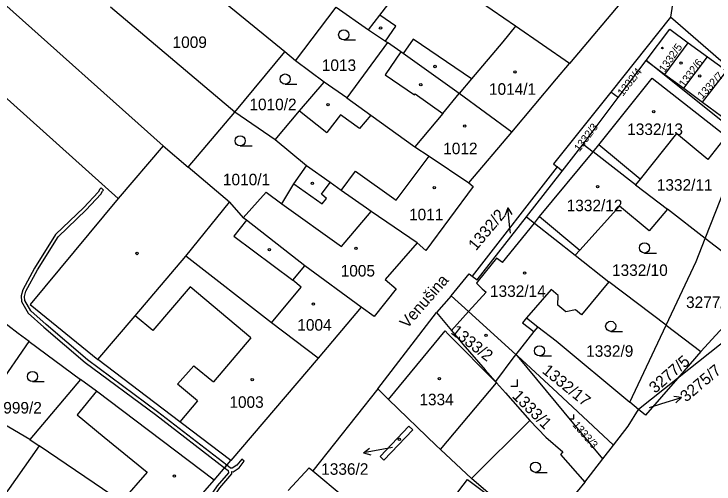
# Model space of a CAD drawing. Extents: x -600849 to -599899, y -1204328 to -1203436.
# Drawn here: x -600187.5 to -600084.4, y -1203603.2 to -1203534 of the extents above; entities that cross this region are included whole.
import ezdxf

# ---------------------------------------------------------------- set-up
doc = ezdxf.new("R2010")
doc.units = 0
for name, color, linetype in [('Vrstva 1', 7, 'Continuous'), ('Vrstva 13', 7, 'Continuous'), ('Vrstva 2', 7, 'Continuous'), ('Vrstva 3', 7, 'Continuous'), ('Vrstva 4', 7, 'Continuous'), ('Vrstva 5', 7, 'Continuous'), ('Vrstva 7', 7, 'Continuous')]:
    doc.layers.add(name, color=color, linetype=linetype)

msp = doc.modelspace()

# ---------------------------------------------------------------- linework, layer by layer
at = {"layer": 'Vrstva 1'}
for p, q in [((-600088.22, -1203518.34), (-600090.77, -1203534.42)), ((-600147.59, -1203539.56), (-600166.14, -1203524.37)), ((-600096.63, -1203530.54), (-600105.64, -1203541.26)), ((-600154.95, -1203548.45), (-600173.29, -1203532.96)), ((-600146.02, -1203540.85), (-600140.01, -1203532.98)), ((-600140.01, -1203532.98), (-600135.28, -1203536.29)), ((-600090.77, -1203534.42), (-600099.57, -1203545.46)), ((-600077.65, -1203545.83), (-600090.77, -1203534.42)), ((-600132.47, -1203538.17), (-600138.44, -1203546.32)), ((-600130.49, -1203539.53), (-600132.47, -1203538.17)), ((-600091.58, -1203542.86), (-600088.16, -1203538.23)), ((-600088.16, -1203538.23), (-600085.32, -1203540.29)), ((-600154.95, -1203548.45), (-600147.59, -1203539.56)), ((-600146.02, -1203540.85), (-600147.59, -1203539.56)), ((-600141.8, -1203544), (-600146.02, -1203540.85)), ((-600098.47, -1203546.28), (-600094.36, -1203540.81)), ((-600094.36, -1203540.81), (-600091.58, -1203542.86)), ((-600080.84, -1203551.64), (-600094.36, -1203540.81)), ((-600088.8, -1203544.91), (-600085.32, -1203540.29)), ((-600085.32, -1203540.29), (-600082.46, -1203542.35)), ((-600107.54, -1203543.52), (-600105.64, -1203541.26)), ((-600091.58, -1203542.86), (-600088.8, -1203544.91)), ((-600086.05, -1203546.94), (-600082.46, -1203542.35)), ((-600138.44, -1203546.32), (-600141.8, -1203544)), ((-600114.12, -1203551.39), (-600107.54, -1203543.52)), ((-600088.8, -1203544.91), (-600086.05, -1203546.94)), ((-600098.47, -1203546.28), (-600099.57, -1203545.46)), ((-600103.65, -1203553.16), (-600098.47, -1203546.28)), ((-600086.05, -1203546.94), (-600083.23, -1203549.02)), ((-600149.03, -1203552.52), (-600154.95, -1203548.45)), ((-600120.49, -1203558.87), (-600114.12, -1203551.39)), ((-600144.41, -1203556.36), (-600149.03, -1203552.52)), ((-600106.74, -1203557.12), (-600103.65, -1203553.16)), ((-600103.65, -1203553.16), (-600102.18, -1203554.3)), ((-600095.91, -1203559.13), (-600102.18, -1203554.3)), ((-600085.66, -1203567.04), (-600080.38, -1203553.65)), ((-600107.48, -1203556.49), (-600119.97, -1203572.62)), ((-600111.99, -1203563.84), (-600106.74, -1203557.12)), ((-600106.74, -1203557.12), (-600107.48, -1203556.49)), ((-600095.91, -1203559.13), (-600091.22, -1203562.75)), ((-600162.19, -1203569.64), (-600155.76, -1203561.69)), ((-600155.76, -1203561.69), (-600153.74, -1203564)), ((-600085.66, -1203567.04), (-600091.22, -1203562.75)), ((-600186.88, -1203581.05), (-600208.82, -1203564.15)), ((-600077.11, -1203573.64), (-600085.66, -1203567.04)), ((-600104.82, -1203569.52), (-600099.85, -1203573.46)), ((-600136.36, -1203577.15), (-600144.64, -1203571.07)), ((-600091.41, -1203579.85), (-600099.85, -1203573.46)), ((-600077.11, -1203573.64), (-600086.3, -1203583.72)), ((-600072.84, -1203574.2), (-600089.73, -1203587.68)), ((-600123.08, -1203575.5), (-600125.26, -1203577.97)), ((-600136.36, -1203577.15), (-600142.67, -1203584.7)), ((-600133.89, -1203589.22), (-600125.26, -1203577.97)), ((-600096.73, -1203591.19), (-600091.41, -1203579.85)), ((-600091.41, -1203579.85), (-600086.3, -1203583.72)), ((-600185.28, -1203582.21), (-600186.88, -1203581.05)), ((-600192.36, -1203592.5), (-600185.28, -1203582.21)), ((-600185.28, -1203582.21), (-600177.68, -1203587.81)), ((-600121.34, -1203582.61), (-600118.07, -1203586.41)), ((-600113.54, -1203584.13), (-600113.3, -1203584.33)), ((-600086.3, -1203583.72), (-600089.73, -1203587.68)), ((-600142.67, -1203584.7), (-600155.53, -1203599.75)), ((-600100.72, -1203599.54), (-600113.3, -1203584.33)), ((-600118.07, -1203586.41), (-600116.55, -1203588.13)), ((-600177.68, -1203587.81), (-600185.17, -1203596.68)), ((-600116.55, -1203588.13), (-600116.38, -1203588.32)), ((-600089.73, -1203587.68), (-600095.46, -1203592.25)), ((-600133.89, -1203589.22), (-600143.47, -1203601.31)), ((-600095.46, -1203592.25), (-600096.73, -1203591.19)), ((-600185.17, -1203596.68), (-600192.36, -1203592.5)), ((-600097, -1203594.73), (-600095.46, -1203592.25)), ((-600155.53, -1203599.75), (-600162.86, -1203594.2)), ((-600120.07, -1203602.44), (-600111.47, -1203593.9)), ((-600099.16, -1203597.53), (-600097, -1203594.73)), ((-600183.79, -1203597.62), (-600190.77, -1203607.52)), ((-600185.17, -1203596.68), (-600183.79, -1203597.62)), ((-600100.72, -1203599.54), (-600099.16, -1203597.53)), ((-600158.02, -1203602.67), (-600155.53, -1203599.75)), ((-600103.38, -1203602.99), (-600100.72, -1203599.54)), ((-600143.47, -1203601.31), (-600139.01, -1203605.01)), ((-600165.19, -1203610.87), (-600158.02, -1203602.67)), ((-600114.6, -1203607.12), (-600120.07, -1203602.44)), ((-600103.38, -1203602.99), (-600110.42, -1203611.48))]:
    msp.add_line(p, q, dxfattribs=at)
for points in [[(-600105.64, -1203541.26), (-600113.61, -1203535.76), (-600122.21, -1203529.82)], [(-600135.28, -1203536.29), (-600132.77, -1203537.97), (-600132.47, -1203538.17)], [(-600094.36, -1203540.81), (-600090.84, -1203536.22), (-600088.16, -1203538.23)], [(-600114.12, -1203551.39), (-600121.92, -1203545.7), (-600130.13, -1203539.79), (-600130.49, -1203539.53)], [(-600149.03, -1203552.52), (-600145.42, -1203548.24), (-600141.8, -1203544)], [(-600102.18, -1203554.3), (-600101.32, -1203553.26), (-600093.47, -1203543.4), (-600082.56, -1203551.95), (-600085.25, -1203555.41), (-600089.86, -1203551.56), (-600095.24, -1203558.29), (-600095.91, -1203559.13)], [(-600099.57, -1203545.46), (-600108, -1203556.04), (-600107.48, -1203556.49)], [(-600138.44, -1203546.32), (-600134.94, -1203548.85), (-600128.45, -1203553.54), (-600126.33, -1203554.94), (-600120.49, -1203558.87)], [(-600155.76, -1203561.69), (-600161.82, -1203556.56), (-600154.95, -1203548.45)], [(-600153.74, -1203564), (-600150.35, -1203560.2), (-600148.03, -1203561.92), (-600146.27, -1203559), (-600144.41, -1203556.36)], [(-600135.54, -1203562.6), (-600139.28, -1203559.96), (-600140.91, -1203558.81), (-600144.41, -1203556.36)], [(-600120.49, -1203558.87), (-600119.84, -1203559.41), (-600126.79, -1203568.8), (-600128.11, -1203567.7)], [(-600128.11, -1203567.7), (-600134.85, -1203563.07), (-600135.54, -1203562.6)], [(-600091.22, -1203562.75), (-600093.9, -1203565.92), (-600098.3, -1203562.3), (-600104.13, -1203568.75), (-600104.82, -1203569.52)], [(-600144.64, -1203571.07), (-600153.26, -1203564.37), (-600153.74, -1203564)], [(-600119.97, -1203572.62), (-600119.26, -1203573.16), (-600111.99, -1203563.84)], [(-600111.99, -1203563.84), (-600110.82, -1203564.77), (-600104.82, -1203569.52)], [(-600128.11, -1203567.7), (-600132.82, -1203573.1), (-600131.18, -1203574.47), (-600134.42, -1203578.53), (-600136.36, -1203577.15)], [(-600091.41, -1203579.85), (-600087, -1203570.44), (-600085.66, -1203567.04)], [(-600162.86, -1203594.2), (-600163.04, -1203594.06), (-600175.13, -1203584.91), (-600169.65, -1203578.45), (-600162.19, -1203569.64)], [(-600142.67, -1203584.7), (-600149.53, -1203579.47), (-600162.19, -1203569.64)], [(-600123.08, -1203575.5), (-600120.41, -1203572.28), (-600119.97, -1203572.62)], [(-600099.85, -1203573.46), (-600103.86, -1203578.3), (-600104.76, -1203577.58), (-600106.2, -1203577.88), (-600107.34, -1203576.87), (-600107.31, -1203575.45), (-600108.35, -1203574.59), (-600112, -1203578.76), (-600110.3, -1203580.07)], [(-600113.54, -1203584.13), (-600120.52, -1203577.81), (-600123.08, -1203575.5)], [(-600125.26, -1203577.97), (-600123.03, -1203580.61), (-600121.34, -1203582.61)], [(-600110.3, -1203580.07), (-600110.88, -1203580.78), (-600113.54, -1203584.13)], [(-600110.3, -1203580.07), (-600107.62, -1203582.12), (-600096.73, -1203591.19)], [(-600113.54, -1203584.13), (-600113.84, -1203584.51), (-600116.55, -1203588.13)], [(-600113.3, -1203584.33), (-600107.41, -1203589.8), (-600099.16, -1203597.53)], [(-600158.02, -1203602.67), (-600175.36, -1203589.53), (-600177.68, -1203587.81)], [(-600116.38, -1203588.32), (-600115.05, -1203589.82), (-600111.47, -1203593.9)], [(-600089.73, -1203587.68), (-600094.44, -1203593.11), (-600095.46, -1203592.25)], [(-600120.07, -1203602.44), (-600124.65, -1203598.17), (-600125.28, -1203597.58), (-600132.29, -1203590.78), (-600133.89, -1203589.22)], [(-600111.47, -1203593.9), (-600109.12, -1203596.33), (-600106.62, -1203598.5), (-600106.99, -1203598.89), (-600103.38, -1203602.99)], [(-600133.55, -1203599.18), (-600129.32, -1203594.69), (-600128.74, -1203595.24), (-600132.98, -1203599.73), (-600133.55, -1203599.18)], [(-600165.19, -1203610.87), (-600166.28, -1203610.07), (-600171.71, -1203605.84), (-600183.79, -1203597.62)], [(-600147.11, -1203604.19), (-600144.02, -1203600.86), (-600143.47, -1203601.31)], [(-600124.82, -1203609.64), (-600125.58, -1203609.03), (-600120.68, -1203602.55), (-600114.6, -1203607.12)]]:
    msp.add_lwpolyline(points, dxfattribs=at)
at = {"layer": 'Vrstva 13'}
for points in [[(-600156.46, -1203600.85), (-600156.14, -1203600.47), (-600166.33, -1203592.61), (-600176.67, -1203584.93), (-600182.78, -1203579.74), (-600185.02, -1203577.73), (-600185.91, -1203576.18), (-600185.95, -1203575.58), (-600185.75, -1203574.8), (-600184.05, -1203571.68), (-600180.98, -1203566.79), (-600176.84, -1203562.85), (-600174.69, -1203560.52), (-600174.44, -1203560.08), (-600174.3, -1203559.92), (-600174.67, -1203559.59), (-600174.86, -1203559.8), (-600175.09, -1203560.22), (-600177.2, -1203562.49), (-600181.38, -1203566.47), (-600184.49, -1203571.42), (-600186.21, -1203574.62), (-600186.45, -1203575.52), (-600186.41, -1203576.32), (-600185.42, -1203578.05), (-600183.1, -1203580.12), (-600176.99, -1203585.33), (-600166.63, -1203593.01)], [(-600156.14, -1203600.47), (-600156.46, -1203600.85), (-600155.94, -1203601.25), (-600155.91, -1203601.57), (-600157.56, -1203603.49), (-600158.19, -1203604.43), (-600157.77, -1203604.71), (-600157.16, -1203603.79), (-600155.39, -1203601.73), (-600155.42, -1203601.4), (-600155.22, -1203601.43), (-600154.34, -1203600.84), (-600153.56, -1203599.88), (-600153.94, -1203599.56), (-600154.68, -1203600.46), (-600155.34, -1203600.91), (-600155.6, -1203600.88)]]:
    msp.add_lwpolyline(points, close=True, dxfattribs=at)
at = {"layer": 'Vrstva 3'}
for p, q in [((-600138.91, -1203537.79), (-600137.16, -1203537.79)), ((-600147.55, -1203544.3), (-600145.8, -1203544.3)), ((-600154.17, -1203553.4), (-600152.42, -1203553.4)), ((-600094.59, -1203569.19), (-600092.84, -1203569.19)), ((-600099.57, -1203580.74), (-600097.82, -1203580.74)), ((-600110.06, -1203584.36), (-600108.31, -1203584.36)), ((-600184.78, -1203588.15), (-600183.03, -1203588.15)), ((-600113.3, -1203588.81), (-600113.3, -1203587.81)), ((-600114.3, -1203588.81), (-600113.3, -1203588.81)), ((-600104.99, -1203593.64), (-600104.99, -1203592.97)), ((-600105.66, -1203593.64), (-600104.99, -1203593.64)), ((-600110.66, -1203601.52), (-600108.91, -1203601.52))]:
    msp.add_line(p, q, dxfattribs=at)
for centre in [(-600138.91, -1203537.04), (-600147.55, -1203543.55), (-600154.17, -1203552.65), (-600094.59, -1203568.44), (-600099.57, -1203579.99), (-600110.06, -1203583.61), (-600184.78, -1203587.4), (-600110.66, -1203600.77)]:
    msp.add_circle(centre, 0.75, dxfattribs=at)
at = {"layer": 'Vrstva 4'}
for p, q in [((-600208.66, -1203514.74), (-600165.52, -1203553.41)), ((-600172.13, -1203561.16), (-600216.52, -1203521.33)), ((-600133.61, -1203534.12), (-600129.29, -1203528.52)), ((-600135.28, -1203536.29), (-600133.61, -1203534.12)), ((-600131.24, -1203535.78), (-600133.61, -1203534.12)), ((-600132.77, -1203537.97), (-600131.24, -1203535.78)), ((-600113.61, -1203535.76), (-600115.46, -1203538.06)), ((-600128.66, -1203537.65), (-600130.13, -1203539.79)), ((-600120.09, -1203543.53), (-600128.66, -1203537.65)), ((-600115.46, -1203538.06), (-600120.09, -1203543.53)), ((-600130.49, -1203539.53), (-600132.82, -1203542.93)), ((-600132.82, -1203542.93), (-600128.48, -1203545.86)), ((-600120.09, -1203543.53), (-600121.92, -1203545.7)), ((-600128.48, -1203545.86), (-600128.37, -1203545.73)), ((-600128.37, -1203545.73), (-600124.32, -1203548.62)), ((-600124.32, -1203548.62), (-600121.92, -1203545.7)), ((-600145.42, -1203548.24), (-600141.41, -1203551.42)), ((-600139.38, -1203548.82), (-600141.41, -1203551.42)), ((-600136.61, -1203550.86), (-600139.38, -1203548.82)), ((-600134.94, -1203548.85), (-600136.61, -1203550.86)), ((-600124.32, -1203548.62), (-600128.45, -1203553.54)), ((-600095.24, -1203558.29), (-600101.32, -1203553.26)), ((-600165.52, -1203553.41), (-600172.13, -1203561.16)), ((-600165.52, -1203553.41), (-600161.82, -1203556.56)), ((-600110.06, -1203563.82), (-600102.18, -1203554.3)), ((-600131.2, -1203561.42), (-600126.33, -1203554.94)), ((-600139.28, -1203559.96), (-600137.18, -1203557.13)), ((-600137.18, -1203557.13), (-600131.2, -1203561.42)), ((-600146.27, -1203559), (-600142.08, -1203561.93)), ((-600142.19, -1203560.53), (-600140.91, -1203558.81)), ((-600141.44, -1203561.14), (-600142.19, -1203560.53)), ((-600172.13, -1203561.16), (-600185.13, -1203576.77)), ((-600142.08, -1203561.93), (-600141.44, -1203561.14)), ((-600148.03, -1203561.92), (-600139.23, -1203568.25)), ((-600139.23, -1203568.25), (-600134.85, -1203563.07)), ((-600153.26, -1203564.37), (-600155.09, -1203566.69)), ((-600110.82, -1203564.77), (-600110.06, -1203563.82)), ((-600110.06, -1203563.82), (-600104.13, -1203568.75)), ((-600115.51, -1203570.58), (-600110.82, -1203564.77)), ((-600155.09, -1203566.69), (-600146.39, -1203573.18)), ((-600116.38, -1203569.94), (-600119.1, -1203573.29)), ((-600115.51, -1203570.58), (-600116.38, -1203569.94)), ((-600146.39, -1203573.18), (-600144.64, -1203571.07)), ((-600145.17, -1203574.23), (-600146.39, -1203573.18)), ((-600119.1, -1203573.29), (-600119.37, -1203573.62)), ((-600119.37, -1203573.62), (-600118.52, -1203574.45)), ((-600161.55, -1203574.19), (-600167.03, -1203580.59)), ((-600152.61, -1203581.68), (-600161.55, -1203574.19)), ((-600149.53, -1203579.47), (-600145.17, -1203574.23)), ((-600117.94, -1203574.94), (-600120.52, -1203577.81)), ((-600118.52, -1203574.45), (-600117.94, -1203574.94)), ((-600185.13, -1203576.77), (-600175.13, -1203584.91)), ((-600120.52, -1203577.81), (-600123.03, -1203580.61)), ((-600167.03, -1203580.59), (-600169.65, -1203578.45)), ((-600112, -1203578.76), (-600112.56, -1203579.5)), ((-600112.56, -1203579.5), (-600110.88, -1203580.78)), ((-600132.29, -1203590.78), (-600123.96, -1203580.67)), ((-600123.96, -1203580.67), (-600123.5, -1203581.14)), ((-600123.5, -1203581.14), (-600116.38, -1203588.32)), ((-600152.61, -1203581.68), (-600158.08, -1203588.17)), ((-600163.38, -1203588.51), (-600160.99, -1203585.81)), ((-600160.99, -1203585.81), (-600158.08, -1203588.17)), ((-600124.65, -1203598.17), (-600116.38, -1203588.32)), ((-600160.45, -1203590.99), (-600163.38, -1203588.51)), ((-600175.36, -1203589.53), (-600178.21, -1203593.02)), ((-600160.45, -1203590.99), (-600163.04, -1203594.06)), ((-600178.21, -1203593.02), (-600174.19, -1203596.35)), ((-600174.19, -1203596.35), (-600167.88, -1203601.48)), ((-600167.88, -1203601.48), (-600171.71, -1203605.84))]:
    msp.add_line(p, q, dxfattribs=at)
at = {"layer": 'Vrstva 5'}
for centre, radius in [((-600133.49, -1203536.02), 0.175), ((-600091.96, -1203538.98), 0.117), ((-600125.46, -1203541.7), 0.175), ((-600089.21, -1203541.19), 0.175), ((-600113.68, -1203542.51), 0.175), ((-600086.45, -1203543.09), 0.175), ((-600127.55, -1203544.37), 0.175), ((-600141.22, -1203547.33), 0.175), ((-600093.23, -1203548.35), 0.175), ((-600121.08, -1203550.48), 0.175), ((-600143.53, -1203558.93), 0.175), ((-600125.57, -1203559.57), 0.175), ((-600101.5, -1203559.42), 0.175), ((-600149.86, -1203568.71), 0.175), ((-600137.12, -1203568.51), 0.175), ((-600169.37, -1203569.26), 0.175), ((-600112.25, -1203572.15), 0.175), ((-600143.38, -1203576.71), 0.175), ((-600117.93, -1203581.33), 0.175), ((-600152.4, -1203587.86), 0.175), ((-600124.81, -1203587.7), 0.175), ((-600130.71, -1203596.67), 0.175), ((-600163.87, -1203602.07), 0.175)]:
    msp.add_circle(centre, radius, dxfattribs=at)
at = {"layer": 'Vrstva 7'}
for p, q in [((-600114.73, -1203562.55), (-600115.13, -1203563.6)), ((-600114.42, -1203565.54), (-600114.73, -1203562.55)), ((-600114.73, -1203562.55), (-600114.13, -1203563.5)), ((-600114.35, -1203566.28), (-600114.42, -1203565.54)), ((-600089.16, -1203590.51), (-600090.26, -1203590.33)), ((-600093.86, -1203591.94), (-600092.03, -1203591.39)), ((-600092.03, -1203591.39), (-600089.16, -1203590.51)), ((-600089.16, -1203590.51), (-600089.97, -1203591.28)), ((-600136.01, -1203598.62), (-600135.11, -1203597.95)), ((-600133.05, -1203598.1), (-600136.01, -1203598.62)), ((-600136.01, -1203598.62), (-600134.93, -1203598.94)), ((-600131.72, -1203597.88), (-600133.05, -1203598.1))]:
    msp.add_line(p, q, dxfattribs=at)

# ---------------------------------------------------------------- texts
at = {"layer": 'Vrstva 2'}
for s, p in [('1009', (-600164.13, -1203538.97)), ('1013', (-600142.14, -1203542.36)), ('1014/1', (-600117.51, -1203545.87)), ('1010/2', (-600152.81, -1203548.14)), ('1332/13', (-600097.14, -1203551.8)), ('1012', (-600124.25, -1203554.63)), ('1010/1', (-600156.71, -1203559.21)), ('1332/11', (-600092.78, -1203560.01)), ('1332/12', (-600106.06, -1203563.03)), ('1011', (-600129.29, -1203564.37)), ('1332/10', (-600099.38, -1203572.57)), ('1005', (-600139.36, -1203572.66)), ('1332/14', (-600117.36, -1203575.66)), ('3277/3', (-600088.47, -1203577.3)), ('1004', (-600145.75, -1203580.64)), ('1332/9', (-600103.19, -1203584.49)), ('1003', (-600155.76, -1203592.01)), ('1334', (-600127.76, -1203591.63)), ('999/2', (-600189.08, -1203592.85)), ('1336/2', (-600142.23, -1203601.88))]:
    msp.add_text(s, height=1.7, dxfattribs=at).set_placement(p)
for s, height, rotation, p in [('1332/5', 1.14, 55, (-600091.63, -1203542.65)), ('1332/6', 1.14, 53, (-600088.72, -1203544.85)), ('1332/4', 1.14, 52, (-600097.77, -1203546.15)), ('1332/7', 1.14, 47, (-600086.07, -1203546.56)), ('1332/3', 1.14, 53, (-600104.18, -1203554.34)), ('1332/2', 1.7, 50, (-600119.43, -1203568.96)), ('1333/2', 1.7, 322, (-600123.24, -1203580.99)), ('3277/5', 1.7, 41, (-600093.02, -1203589.96)), ('1332/17', 1.7, 321, (-600109.8, -1203586.76)), ('3275/7', 1.7, 40, (-600088.46, -1203591.24)), ('1333/1', 1.7, 315, (-600114.2, -1203590.39)), ('1333/3', 1.14, 311, (-600105.26, -1203594.59))]:
    msp.add_text(s, height=height, rotation=rotation, dxfattribs=at).set_placement(p)
at = {"layer": 'Vrstva 7'}
msp.add_text('Venušina', height=1.7, rotation=49, dxfattribs=at).set_placement((-600129.56, -1203580.42))

doc.saveas('drawing.dxf')
